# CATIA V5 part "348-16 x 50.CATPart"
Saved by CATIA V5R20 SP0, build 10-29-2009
Part number: 348-16 x 50
Definition: NONE
Nomenclature: 348-16 x 50
Source: Unknown
Description: 348-16 x 50
Bounding box of the stored display mesh (mm): x 0 to 50, y -13 to 13, z -13 to 13
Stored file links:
  C:\Users\Utente\Desktop\IO LAVORO\3D X SITO CF\X SITO\3D files 348\348-16 x 50.CATPart
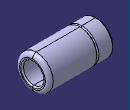
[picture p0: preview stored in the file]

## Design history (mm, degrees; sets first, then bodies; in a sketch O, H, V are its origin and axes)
Body1 "348-16 x 50" (main body)
  Solid1: solid without history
